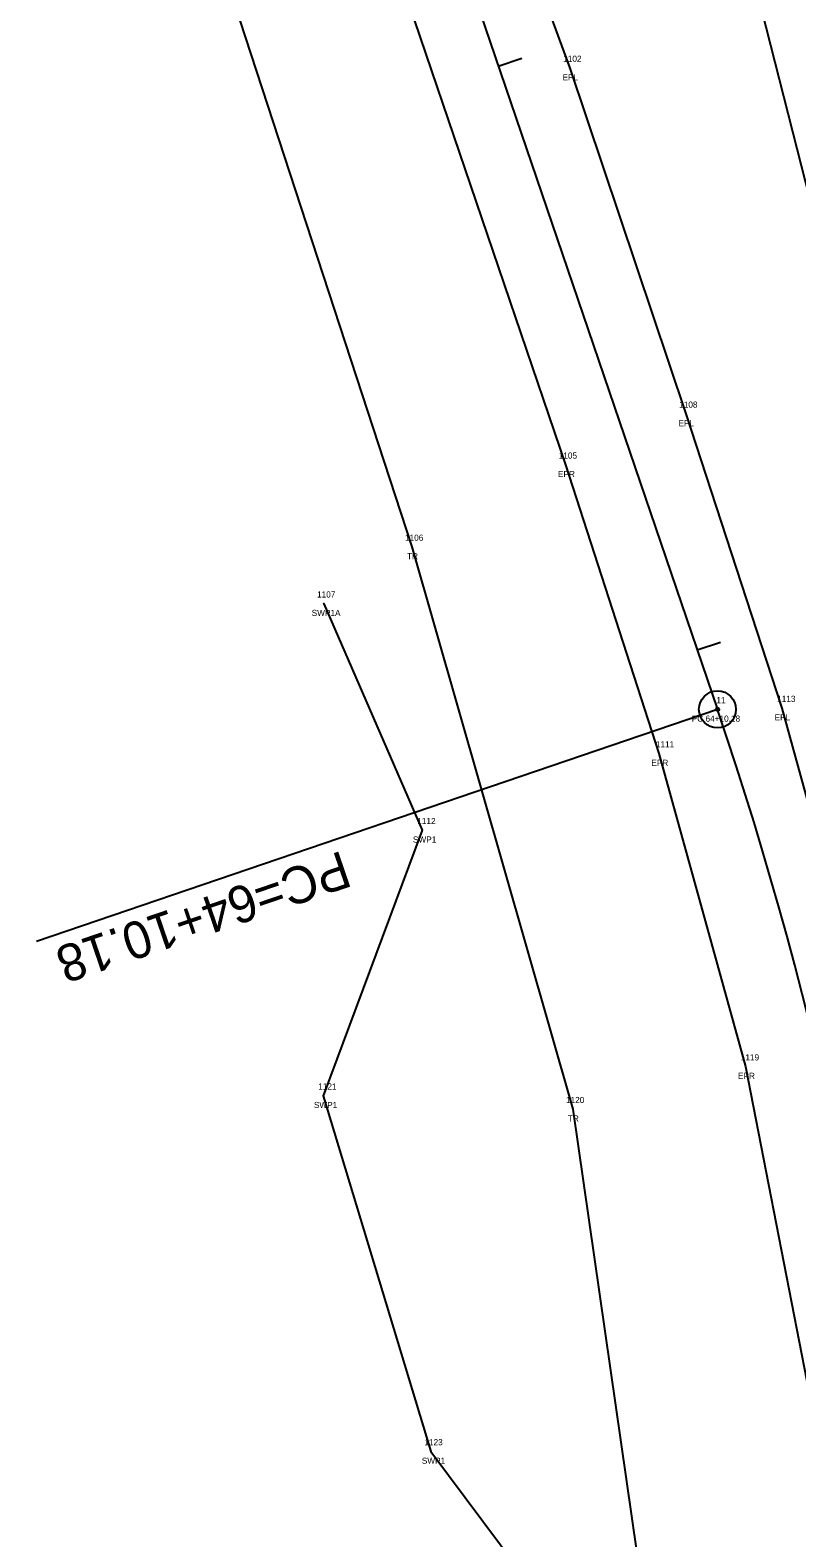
# Model space of a CAD drawing. Extents: x 2432632 to 2433497, y 684847 to 688233.
# Drawn here: x 2433011.9 to 2433136.2, y 686295.7 to 686540.2 of the extents above; entities that cross this region are included whole.
import ezdxf

# ---------------------------------------------------------------- set-up
doc = ezdxf.new("R2010")
doc.units = 0
for name, color, linetype in [('RD_EX_H2O', 7, 'Continuous'), ('RD_EX_H2O_txCode', 7, 'Continuous'), ('RD_EX_Road', 7, 'Continuous'), ('RD_EX_Road_txCode', 7, 'Continuous'), ('RD_EX_VEG', 7, 'Continuous'), ('RD_EX_VEG_txCode', 7, 'Continuous'), ('RD_HC_Cl', 7, 'Continuous'), ('RD_HC_Data', 7, 'Continuous'), ('RD_HC_Data_Tic', 7, 'Continuous'), ('RD_HC_txCode', 7, 'Continuous'), ('RD_SMD_Locator', 7, 'Continuous')]:
    doc.layers.add(name, color=color, linetype=linetype)

msp = doc.modelspace()

# ---------------------------------------------------------------- linework, layer by layer
at = {"layer": 'RD_EX_H2O'}
msp.add_lwpolyline([(2433059.53, 686447.22), (2433075.46, 686410.47), (2433059.4, 686367.42), (2433076.9, 686309.73), (2433110.63, 686264.52), (2433114.63, 686215.04), (2433113.03, 686166.79), (2433114.46, 686111.82), (2433110.48, 686084.68), (2433120.95, 686072.12)], dxfattribs=at)
at = {"layer": 'RD_EX_Road'}
for points in [[(2433066.06, 686565.78), (2433098.73, 686469.74), (2433113.88, 686422.91), (2433127.93, 686372.14), (2433139.1, 686314.76), (2433144.47, 686268.02), (2433145.44, 686213), (2433142.32, 686164.92), (2433135.44, 686115.75), (2433128.09, 686081.14)], [(2433088.99, 686562.5), (2433099.45, 686534.09), (2433118.26, 686478), (2433133.83, 686430.29), (2433148.35, 686377.56), (2433159.33, 686322.19), (2433165.5, 686270.06), (2433166.43, 686212.82), (2433163.02, 686162.81), (2433156.19, 686111.14), (2433152.88, 686076.43)]]:
    msp.add_lwpolyline(points, dxfattribs=at)
at = {"layer": 'RD_EX_VEG'}
for points in [[(2433112.43, 688094.61), (2433041.17, 687898.89), (2432988.9, 687699.78), (2432947.96, 687578.08), (2432935.9, 687556.87), (2432944.3, 687538.7), (2432913.88, 687397.98), (2432902.4, 687330.02), (2432885.78, 687157.56), (2432894.43, 687032.93), (2432918.07, 686924.4), (2432974.73, 686759.54), (2433073.82, 686456.42), (2433099.9, 686365.23), (2433115.47, 686257.21), (2433114.64, 686158.77), (2433095.68, 686092.78)], [(2433166.25, 688082.87), (2433111.93, 687876.69), (2433067.75, 687703.46), (2433065.05, 687678.03), (2433052.74, 687645.62), (2433005.45, 687469.88), (2432979.96, 687326.61), (2432966.8, 687267.34), (2432959.05, 687210.65), (2432959.25, 687071.62), (2432974.82, 687014.37), (2432998.13, 686938.9), (2433012.99, 686878.7), (2433054.45, 686782.35), (2433123.54, 686586.06), (2433129.82, 686546.35), (2433158.34, 686434.26), (2433192.79, 686274.67), (2433189.42, 686162.6), (2433197.4, 686074.41)]]:
    msp.add_lwpolyline(points, dxfattribs=at)
at = {"layer": 'RD_HC_Cl'}
msp.add_line((2432974.01, 686868.39), (2433123.37, 686430.08), dxfattribs=at)
msp.add_arc((2432536.11, 686229.97), 620.41, 350.43349, 18.81644, dxfattribs=at)
at = {"layer": 'RD_HC_Data'}
msp.add_line((2433123.37, 686430.08), (2433012.92, 686392.44), dxfattribs=at)
for radius in [3, 0.282]:
    msp.add_circle((2433123.37, 686430.08), radius, dxfattribs=at)
at = {"layer": 'RD_HC_Data_Tic'}
for p, q in [((2433087.83, 686534.37), (2433091.62, 686535.66)), ((2433120.09, 686439.71), (2433123.87, 686441))]:
    msp.add_line(p, q, dxfattribs=at)
at = {"layer": 'RD_SMD_Locator'}
for centre in [(2433099.45, 686534.09), (2433118.26, 686478), (2433098.73, 686469.74), (2433073.82, 686456.42), (2433059.53, 686447.22), (2433123.37, 686430.08), (2433133.83, 686430.29), (2433113.88, 686422.91), (2433075.46, 686410.47), (2433127.93, 686372.14), (2433059.4, 686367.42), (2433099.9, 686365.23), (2433076.9, 686309.73)]:
    msp.add_circle(centre, 0.001, dxfattribs=at)

# ---------------------------------------------------------------- texts
at = {"layer": 'RD_EX_H2O_txCode'}
for s, p in [('1107', (2433058.43, 686448.22)), ('SWP1A', (2433057.56, 686445.22)), ('1112', (2433074.68, 686411.47)), ('SWP1', (2433073.98, 686408.47)), ('1121', (2433058.62, 686368.42)), ('SWP1', (2433057.92, 686365.42)), ('1123', (2433075.84, 686310.73)), ('SWP1', (2433075.42, 686307.73))]:
    msp.add_text(s, height=1, dxfattribs=at).set_placement(p)
at = {"layer": 'RD_EX_Road_txCode'}
for s, p in [('1102', (2433098.35, 686535.09)), ('EPL', (2433098.24, 686532.09)), ('1108', (2433117.16, 686479)), ('EPL', (2433117.05, 686476)), ('1105', (2433097.63, 686470.74)), ('EPR', (2433097.5, 686467.74)), ('1113', (2433133.05, 686431.29)), ('EPL', (2433132.63, 686428.29)), ('1111', (2433113.38, 686423.91)), ('EPR', (2433112.65, 686420.91)), ('1119', (2433127.15, 686373.14)), ('EPR', (2433126.7, 686370.14))]:
    msp.add_text(s, height=1, dxfattribs=at).set_placement(p)
at = {"layer": 'RD_EX_VEG_txCode'}
for s, p in [('1106', (2433072.69, 686457.42)), ('TR', (2433073.02, 686454.42)), ('1120', (2433098.8, 686366.23)), ('TR', (2433099.11, 686363.23))]:
    msp.add_text(s, height=1, dxfattribs=at).set_placement(p)
at = {"layer": 'RD_HC_Data'}
msp.add_text('PC=64+10.18', height=6, rotation=198.8164, dxfattribs=at).set_placement((2433062.49, 686407.22))
at = {"layer": 'RD_HC_txCode'}
for s, p in [('11', (2433123.2, 686431.08)), ('PC 64+10.18', (2433119.2, 686428.08))]:
    msp.add_text(s, height=1, dxfattribs=at).set_placement(p)

doc.saveas('drawing.dxf')
